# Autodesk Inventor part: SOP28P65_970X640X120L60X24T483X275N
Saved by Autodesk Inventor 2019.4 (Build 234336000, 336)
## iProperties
Created: 2021-02
Part Number: SOP28P65_970X640X120L60X24T483X275N
Material: Generic
Document SubType Name: Modeling
Designer: Administrator
Density: 1 g/cm^3
Appearance: Default
Title: SOP28P65_970X640X120L60X24T483X275N
Author: Administrator
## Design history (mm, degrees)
feature "Body1"
body "Solid1"
